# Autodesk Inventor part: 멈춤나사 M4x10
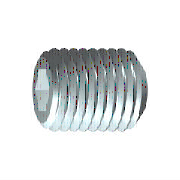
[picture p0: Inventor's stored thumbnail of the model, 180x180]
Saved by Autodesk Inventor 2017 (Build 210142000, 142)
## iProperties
Created: 2012-02
Part Number: 멈춤나사 M4x10
Material: 강철, 연강
Description: 6각 소켓 머리 없는 멈춤 나사
Document SubType Name: Modeling
Standard: KS B 1028
Designer: mduedu
Standards Organization: KS
Language: ko-KR
Size Designation: 납작점M4x10
Categories: <MemberInstance><Categories><Category DisplayName="조임쇠" InternalName="e4da775c-781d-43d5-af7c-5136215cf5a6" Mnemonic="FSTN"><Category DisplayName="볼트" InternalN
Density: 1 g/cm^3
Appearance: 강철
IsCustomPart: 1
Author: mduedu
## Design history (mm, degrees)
sketch "스케치1"
  geometry: L1 (0, 0)-(6.833, 0); L2 (10, 1.155)-(10, 2); L3 (10, 2)-(0, 2); L4 (10, 1.155)-(7.5, 1.155); L5 (7.5, 1.155)-(6.833, 0); L6 (0, -0.4)-(0, 2.4) reference; L7 (0, 2)-(0, 0)
  constraints: 13 end point, 3 parallel, 1 collinear, 1 perpendicular, 1 point on line
  dimensions: "d0" = 2.5 distance of L2.start L4.end (= INTI); "d1" = 60 deg angle of L5 L1; "d2" = 4 diameter of L3 L1 (= NND); "d3" = 2.3094 diameter of L4 L1 (= 1.1547 x SW); "d5" = 10 distance from line of L2 L3.end (= NLG)
revolve "본체" sketch "스케치1" stored, may be unused: angle "d6" = 90 deg
sketch "스케치2"
  geometry: L1 (-0.577, 1)-(0.577, 1); L2 (0.577, 1)-(1.155, 0); L3 (1.155, 0)-(0.577, -1); L4 (0.577, -1)-(-0.577, -1); L5 (-0.577, -1)-(-1.155, 0); L6 (-1.155, 0)-(-0.577, 1); A1 r 1.155 centre (0, 0) between (-0.577, 1) and (0.577, 1) reference; 2 further points
  constraints: 12 end point, 2 point on circle, 1 coincident, 1 horizontal, 11 other
extrude "슬롯" join sketch "스케치2" taper "d9" = 0 deg; stored distance "d21" = 10
workaxis "Work Axis1"
workplane "Work Plane1"
body "Solid1"
chamfer "모따기1" distance "d7" = 0.42941 (= -0.5 x GD1 + 0.5 x NND); stored, may be unused: angle "d8" = 45 deg (= FAWI), second distance "d29" = 0.42941 (= -0.5 x GD1 + 0.5 x NND)
feature "스레드" dims "d11" = 10 (= NLG), "d12" = 0
chamfer "모따기2" distance "d13" = 0.42941 (= -0.5 x GD1 + 0.5 x NND); stored, may be unused: angle "d14" = 45 deg (= FAWI), second distance "d30" = 0.42941 (= -0.5 x GD1 + 0.5 x NND)
other parameters: "NND" = 4 [user parameter; used in 5 equation terms], "NLG" = 10 [user parameter; used in 2 equation terms], "INTI" = 2.5 [user parameter; used in 1 equation term], "FAWI" = 45 deg [user parameter; used in 2 equation terms], "SW" = 2 [user parameter; used in 2 equation terms], "GD1" = 3.14117 (= THREADDIA - 1.2269 x PTC) [user parameter; used in 4 equation terms], "d4" = 0, "FAWI1" = 45 deg [user parameter], "d15" = 0, "d31" = 0, "GUL" = 0.42941 (= 0.61345 x PTC) [user parameter], "SPD" = 2.5 [user parameter], "TPU" = 14.28571 (computed from PTC) [user parameter], "TOA" = 30 deg [user parameter], "THREADDIA" = 4 [user parameter; used in 1 equation term], "PTC" = 0.7 [user parameter; used in 4 equation terms], "GAL" = 0.42941 (= 0.61345 x PTC) [user parameter], "E0" = 2.31 (= 1.155 x SW) [user parameter]
